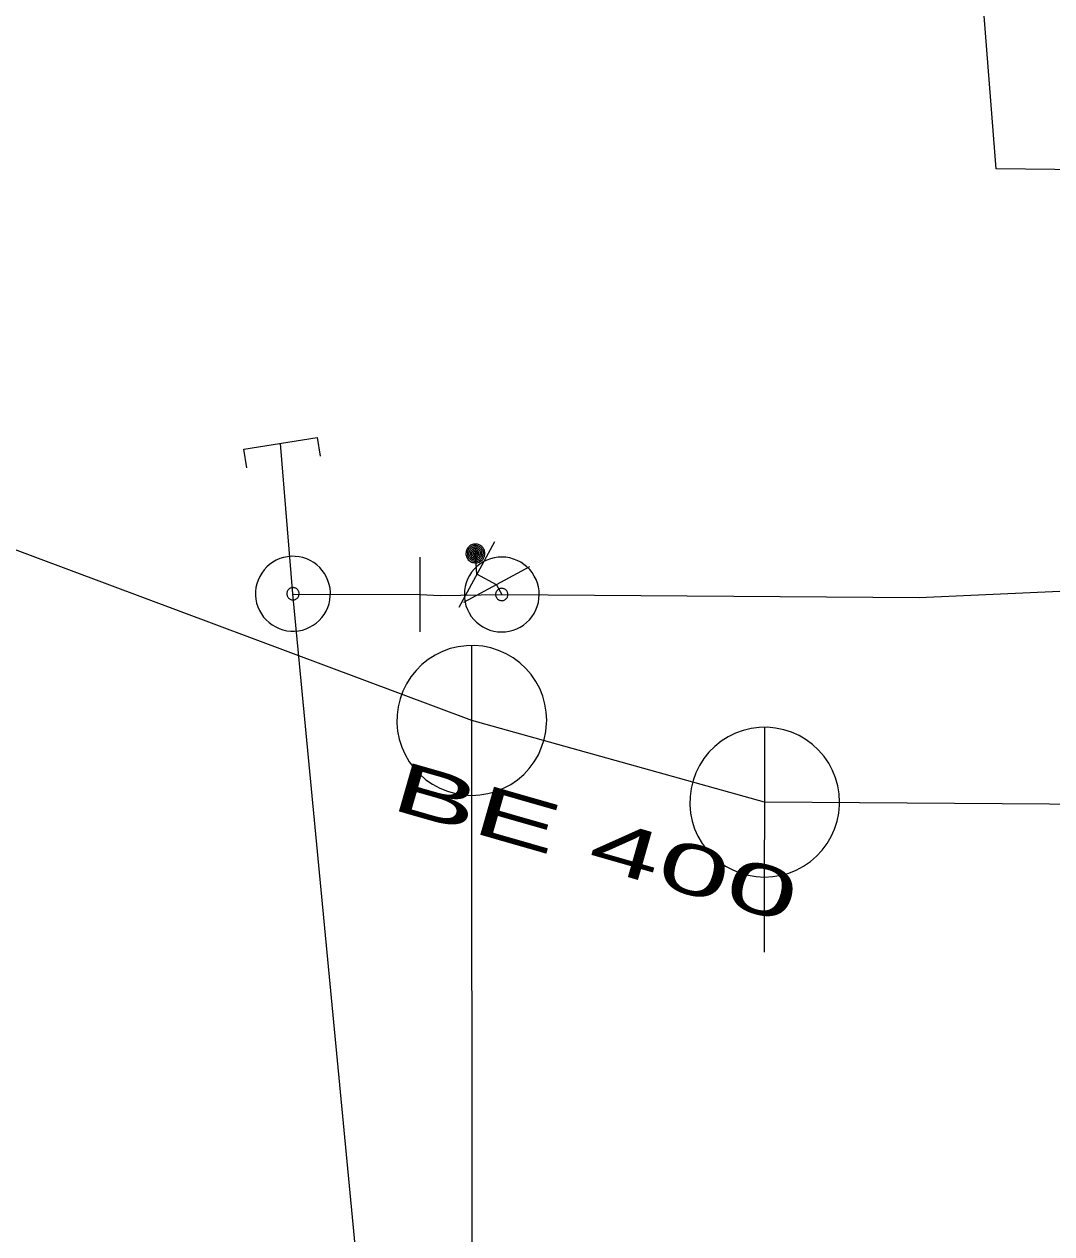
# Model space of a CAD drawing. Extents: x -688432 to -687974, y -973332 to -972704.
# Drawn here: x -688148.91 to -688135.2, y -972935.52 to -972919.38 of the extents above; entities that cross this region are included whole.
import ezdxf
from ezdxf.enums import TextEntityAlignment as Align

# ---------------------------------------------------------------- set-up
doc = ezdxf.new("R2010")
doc.units = 0
doc.header["$LTSCALE"] = 0.27
for name, color, linetype, lineweight in [('1', 7, 'Continuous', 25), ('14', 7, 'Continuous', 25), ('17', 7, 'Continuous', 25), ('22', 7, 'Continuous', 13), ('34', 7, 'Continuous', 13), ('47', 7, 'Continuous', 13), ('9', 7, 'Continuous', 13)]:
    doc.layers.add(name, color=color, linetype=linetype, lineweight=lineweight)

msp = doc.modelspace()

# ---------------------------------------------------------------- linework, layer by layer
at = {"layer": '1'}
msp.add_lwpolyline([(-688157.895, -972985.064), (-688131.748, -972983.489), (-688134.952, -972934.372), (-688122, -972934.52), (-688122.986, -972921.456), (-688135.938, -972921.308), (-688137.958, -972895.554), (-688157.714, -972894.909), (-688157.93, -972929.126), (-688173.215, -972938.189), (-688162.29, -972954.057)], close=True, dxfattribs=at)
at = {"layer": '14'}
for p, q in [((-688142.939, -972928.669), (-688206.6, -972904.874)), ((-688142.909, -972965.839), (-688142.939, -972928.669)), ((-688139.03, -972929.76), (-688142.939, -972928.669))]:
    msp.add_line(p, q, dxfattribs=at)
at = {"layer": '14', "lineweight": 13}
for p, q in [((-688142.609, -972926.859), (-688142.539, -972926.989)), ((-688143.629, -972926.989), (-688145.33, -972926.993))]:
    msp.add_line(p, q, dxfattribs=at)
msp.add_lwpolyline([(-688142.609, -972926.859), (-688142.87, -972926.719), (-688142.89, -972926.44)], dxfattribs=at)
at = {"layer": '14'}
msp.add_lwpolyline([(-688124.05, -972929.87), (-688127.949, -972929.829), (-688134.59, -972929.789), (-688139.03, -972929.76)], dxfattribs=at)
at = {"layer": '17'}
msp.add_line((-688145.326, -972926.979), (-688145.493, -972924.972), dxfattribs=at)
for points in [[(-688142.539, -972926.989), (-688136.969, -972927.03), (-688124.52, -972926.469), (-688116.5, -972926.3), (-688115.02, -972926.289), (-688112.359, -972926.21), (-688100.73, -972925.699), (-688087.609, -972926.17), (-688083.969, -972927.539), (-688080.94, -972929.1), (-688078.329, -972931.09), (-688076.37, -972933.14), (-688074.449, -972935.62), (-688070.85, -972940.129), (-688068.85, -972942.57), (-688067.02, -972944.8), (-688063.62, -972948.98), (-688063.329, -972949.34), (-688059.6, -972954.02), (-688058.039, -972955.829), (-688055.76, -972958.48), (-688051.969, -972962.76), (-688050.239, -972964.93)], [(-688050.85, -973016.992), (-688055.169, -973017.307), (-688064.057, -973021.728), (-688087.539, -973032.609), (-688093.627, -973034.653), (-688116.302, -973034.144), (-688128.092, -973024.28), (-688134.442, -973013.736), (-688141.05, -972971.647), (-688145.326, -972926.979)], [(-688143.629, -972926.989), (-688143.359, -972927), (-688142.539, -972926.989)]]:
    msp.add_lwpolyline(points, dxfattribs=at)
at = {"layer": '22'}
for p, q in [((-688142.939, -972930.669), (-688142.938, -972927.669)), ((-688139.03, -972931.76), (-688139.029, -972928.76))]:
    msp.add_line(p, q, dxfattribs=at)
for points in [[(-688141.939, -972928.669), (-688141.944, -972928.56), (-688141.962, -972928.452), (-688141.992, -972928.346), (-688142.032, -972928.245), (-688142.084, -972928.148), (-688142.146, -972928.058), (-688142.218, -972927.975), (-688142.298, -972927.901), (-688142.386, -972927.835), (-688142.48, -972927.78), (-688142.58, -972927.735), (-688142.685, -972927.702), (-688142.792, -972927.68), (-688142.901, -972927.67), (-688143.011, -972927.672), (-688143.119, -972927.686), (-688143.226, -972927.711), (-688143.329, -972927.748), (-688143.427, -972927.797), (-688143.519, -972927.855), (-688143.605, -972927.924), (-688143.682, -972928.001), (-688143.751, -972928.087), (-688143.81, -972928.179), (-688143.858, -972928.277), (-688143.895, -972928.38), (-688143.921, -972928.487), (-688143.935, -972928.595), (-688143.938, -972928.705), (-688143.928, -972928.814), (-688143.907, -972928.921), (-688143.873, -972929.025), (-688143.829, -972929.125), (-688143.774, -972929.22), (-688143.708, -972929.308), (-688143.634, -972929.388), (-688143.551, -972929.46), (-688143.461, -972929.522), (-688143.365, -972929.574), (-688143.263, -972929.615), (-688143.158, -972929.645), (-688143.05, -972929.663), (-688142.94, -972929.669), (-688142.831, -972929.663), (-688142.723, -972929.645), (-688142.618, -972929.616), (-688142.516, -972929.575), (-688142.419, -972929.523), (-688142.329, -972929.461), (-688142.246, -972929.39), (-688142.171, -972929.31), (-688142.106, -972929.222), (-688142.05, -972929.128), (-688142.006, -972929.028), (-688141.972, -972928.924), (-688141.95, -972928.816), (-688141.94, -972928.707)], [(-688138.03, -972929.76), (-688138.035, -972929.651), (-688138.053, -972929.543), (-688138.083, -972929.437), (-688138.123, -972929.336), (-688138.175, -972929.239), (-688138.237, -972929.149), (-688138.309, -972929.066), (-688138.389, -972928.992), (-688138.477, -972928.926), (-688138.571, -972928.871), (-688138.671, -972928.826), (-688138.776, -972928.793), (-688138.883, -972928.771), (-688138.992, -972928.761), (-688139.102, -972928.763), (-688139.21, -972928.777), (-688139.317, -972928.802), (-688139.42, -972928.839), (-688139.518, -972928.888), (-688139.61, -972928.946), (-688139.696, -972929.015), (-688139.773, -972929.092), (-688139.842, -972929.178), (-688139.901, -972929.27), (-688139.949, -972929.368), (-688139.986, -972929.471), (-688140.012, -972929.578), (-688140.026, -972929.686), (-688140.029, -972929.796), (-688140.019, -972929.905), (-688139.998, -972930.012), (-688139.964, -972930.116), (-688139.92, -972930.216), (-688139.865, -972930.311), (-688139.799, -972930.399), (-688139.725, -972930.479), (-688139.642, -972930.551), (-688139.552, -972930.613), (-688139.456, -972930.665), (-688139.354, -972930.706), (-688139.249, -972930.736), (-688139.141, -972930.754), (-688139.031, -972930.76), (-688138.922, -972930.754), (-688138.814, -972930.736), (-688138.709, -972930.707), (-688138.607, -972930.666), (-688138.51, -972930.614), (-688138.42, -972930.552), (-688138.337, -972930.481), (-688138.262, -972930.401), (-688138.197, -972930.313), (-688138.141, -972930.219), (-688138.097, -972930.119), (-688138.063, -972930.015), (-688138.041, -972929.907), (-688138.031, -972929.798)]]:
    msp.add_lwpolyline(points, close=True, dxfattribs=at)
at = {"layer": '34'}
for p, q in [((-688143.106, -972927.159), (-688142.632, -972926.279)), ((-688143.627, -972927.488), (-688143.629, -972926.489)), ((-688142.169, -972926.621), (-688143.049, -972927.095))]:
    msp.add_line(p, q, dxfattribs=at)
at = {"layer": '47'}
msp.add_lwpolyline([(-688145.942, -972925.299), (-688145.982, -972925.051), (-688145.003, -972924.892), (-688144.963, -972925.141)], dxfattribs=at)
for points in [[(-688145.304, -972927.478), (-688145.252, -972927.473), (-688145.2, -972927.463), (-688145.151, -972927.446), (-688145.103, -972927.426), (-688145.057, -972927.4), (-688145.014, -972927.369), (-688144.976, -972927.335), (-688144.94, -972927.296), (-688144.909, -972927.255), (-688144.882, -972927.209), (-688144.86, -972927.162), (-688144.844, -972927.112), (-688144.832, -972927.061), (-688144.827, -972927.009), (-688144.826, -972926.957), (-688144.831, -972926.905), (-688144.841, -972926.853), (-688144.858, -972926.803), (-688144.878, -972926.756), (-688144.904, -972926.71), (-688144.935, -972926.667), (-688144.969, -972926.628), (-688145.008, -972926.592), (-688145.049, -972926.561), (-688145.095, -972926.535), (-688145.142, -972926.513), (-688145.192, -972926.496), (-688145.243, -972926.485), (-688145.295, -972926.48), (-688145.347, -972926.479), (-688145.399, -972926.484), (-688145.451, -972926.494), (-688145.501, -972926.51), (-688145.548, -972926.531), (-688145.594, -972926.557), (-688145.637, -972926.587), (-688145.676, -972926.621), (-688145.712, -972926.66), (-688145.743, -972926.702), (-688145.769, -972926.748), (-688145.791, -972926.795), (-688145.808, -972926.844), (-688145.819, -972926.896), (-688145.824, -972926.948), (-688145.825, -972927), (-688145.82, -972927.052), (-688145.81, -972927.104), (-688145.794, -972927.153), (-688145.773, -972927.201), (-688145.747, -972927.247), (-688145.717, -972927.29), (-688145.683, -972927.328), (-688145.644, -972927.364), (-688145.602, -972927.395), (-688145.556, -972927.422), (-688145.509, -972927.444), (-688145.46, -972927.46), (-688145.408, -972927.472), (-688145.356, -972927.477)], [(-688142.039, -972926.992), (-688142.041, -972926.94), (-688142.049, -972926.888), (-688142.062, -972926.838), (-688142.08, -972926.789), (-688142.104, -972926.742), (-688142.132, -972926.697), (-688142.165, -972926.657), (-688142.202, -972926.62), (-688142.242, -972926.587), (-688142.285, -972926.557), (-688142.332, -972926.533), (-688142.381, -972926.515), (-688142.431, -972926.5), (-688142.483, -972926.492), (-688142.535, -972926.489), (-688142.587, -972926.491), (-688142.639, -972926.499), (-688142.69, -972926.512), (-688142.738, -972926.53), (-688142.785, -972926.554), (-688142.83, -972926.582), (-688142.871, -972926.615), (-688142.908, -972926.652), (-688142.941, -972926.692), (-688142.97, -972926.735), (-688142.994, -972926.782), (-688143.013, -972926.831), (-688143.027, -972926.881), (-688143.035, -972926.933), (-688143.038, -972926.985), (-688143.036, -972927.037), (-688143.028, -972927.089), (-688143.016, -972927.14), (-688142.997, -972927.188), (-688142.973, -972927.235), (-688142.946, -972927.28), (-688142.913, -972927.321), (-688142.876, -972927.358), (-688142.835, -972927.391), (-688142.792, -972927.42), (-688142.745, -972927.444), (-688142.697, -972927.463), (-688142.646, -972927.477), (-688142.594, -972927.485), (-688142.542, -972927.488), (-688142.49, -972927.486), (-688142.438, -972927.478), (-688142.388, -972927.466), (-688142.339, -972927.447), (-688142.292, -972927.423), (-688142.247, -972927.396), (-688142.207, -972927.363), (-688142.17, -972927.326), (-688142.137, -972927.285), (-688142.107, -972927.242), (-688142.083, -972927.195), (-688142.065, -972927.147), (-688142.05, -972927.096), (-688142.042, -972927.044)], [(-688145.322, -972927.06), (-688145.313, -972927.06), (-688145.305, -972927.058), (-688145.297, -972927.055), (-688145.289, -972927.052), (-688145.281, -972927.048), (-688145.275, -972927.042), (-688145.268, -972927.037), (-688145.262, -972927.031), (-688145.257, -972927.024), (-688145.253, -972927.016), (-688145.249, -972927.008), (-688145.246, -972927), (-688145.245, -972926.992), (-688145.243, -972926.984), (-688145.244, -972926.975), (-688145.244, -972926.966), (-688145.246, -972926.958), (-688145.249, -972926.95), (-688145.252, -972926.942), (-688145.256, -972926.934), (-688145.262, -972926.928), (-688145.267, -972926.921), (-688145.273, -972926.915), (-688145.28, -972926.909), (-688145.288, -972926.906), (-688145.296, -972926.902), (-688145.304, -972926.899), (-688145.312, -972926.898), (-688145.32, -972926.896), (-688145.329, -972926.897), (-688145.338, -972926.897), (-688145.346, -972926.899), (-688145.354, -972926.902), (-688145.362, -972926.905), (-688145.37, -972926.909), (-688145.376, -972926.914), (-688145.383, -972926.92), (-688145.389, -972926.926), (-688145.395, -972926.933), (-688145.398, -972926.941), (-688145.402, -972926.949), (-688145.405, -972926.957), (-688145.406, -972926.965), (-688145.408, -972926.973), (-688145.407, -972926.982), (-688145.407, -972926.991), (-688145.405, -972926.999), (-688145.402, -972927.007), (-688145.399, -972927.015), (-688145.395, -972927.023), (-688145.39, -972927.029), (-688145.384, -972927.036), (-688145.378, -972927.042), (-688145.371, -972927.047), (-688145.363, -972927.051), (-688145.355, -972927.055), (-688145.347, -972927.058), (-688145.339, -972927.059), (-688145.331, -972927.061)], [(-688142.457, -972926.989), (-688142.456, -972926.98), (-688142.458, -972926.972), (-688142.46, -972926.964), (-688142.463, -972926.956), (-688142.467, -972926.948), (-688142.472, -972926.941), (-688142.477, -972926.934), (-688142.483, -972926.928), (-688142.49, -972926.923), (-688142.497, -972926.918), (-688142.505, -972926.914), (-688142.513, -972926.911), (-688142.521, -972926.909), (-688142.529, -972926.907), (-688142.538, -972926.907), (-688142.547, -972926.906), (-688142.555, -972926.908), (-688142.563, -972926.91), (-688142.571, -972926.913), (-688142.579, -972926.917), (-688142.586, -972926.922), (-688142.593, -972926.927), (-688142.599, -972926.933), (-688142.605, -972926.94), (-688142.609, -972926.947), (-688142.613, -972926.955), (-688142.616, -972926.963), (-688142.618, -972926.971), (-688142.62, -972926.979), (-688142.62, -972926.988), (-688142.621, -972926.997), (-688142.619, -972927.005), (-688142.617, -972927.013), (-688142.614, -972927.021), (-688142.61, -972927.029), (-688142.606, -972927.036), (-688142.6, -972927.043), (-688142.594, -972927.049), (-688142.587, -972927.055), (-688142.58, -972927.059), (-688142.572, -972927.063), (-688142.564, -972927.066), (-688142.556, -972927.068), (-688142.548, -972927.07), (-688142.539, -972927.07), (-688142.53, -972927.071), (-688142.522, -972927.069), (-688142.514, -972927.067), (-688142.506, -972927.064), (-688142.498, -972927.06), (-688142.491, -972927.056), (-688142.484, -972927.05), (-688142.478, -972927.044), (-688142.473, -972927.037), (-688142.468, -972927.03), (-688142.464, -972927.022), (-688142.461, -972927.014), (-688142.459, -972927.006), (-688142.457, -972926.998)]]:
    msp.add_lwpolyline(points, close=True, dxfattribs=at)
at = {"layer": '9'}
for points in [[(-688143.016, -972926.44), (-688143.016, -972926.453), (-688143.014, -972926.466), (-688143.011, -972926.479), (-688143.006, -972926.491), (-688143, -972926.503), (-688142.993, -972926.514), (-688142.985, -972926.524), (-688142.975, -972926.534), (-688142.965, -972926.542), (-688142.954, -972926.549), (-688142.942, -972926.555), (-688142.93, -972926.56), (-688142.917, -972926.563), (-688142.904, -972926.565), (-688142.891, -972926.567), (-688142.878, -972926.566), (-688142.865, -972926.564), (-688142.852, -972926.561), (-688142.84, -972926.556), (-688142.828, -972926.55), (-688142.817, -972926.543), (-688142.807, -972926.535), (-688142.797, -972926.525), (-688142.789, -972926.515), (-688142.782, -972926.504), (-688142.776, -972926.492), (-688142.771, -972926.48), (-688142.768, -972926.467), (-688142.766, -972926.454), (-688142.764, -972926.441), (-688142.765, -972926.428), (-688142.767, -972926.415), (-688142.77, -972926.402), (-688142.775, -972926.39), (-688142.781, -972926.378), (-688142.788, -972926.367), (-688142.796, -972926.357), (-688142.806, -972926.347), (-688142.816, -972926.339), (-688142.827, -972926.332), (-688142.839, -972926.326), (-688142.851, -972926.321), (-688142.864, -972926.318), (-688142.877, -972926.316), (-688142.89, -972926.315), (-688142.903, -972926.315), (-688142.916, -972926.317), (-688142.929, -972926.32), (-688142.941, -972926.325), (-688142.953, -972926.331), (-688142.964, -972926.338), (-688142.974, -972926.346), (-688142.984, -972926.356), (-688142.992, -972926.366), (-688142.999, -972926.377), (-688143.005, -972926.389), (-688143.01, -972926.401), (-688143.013, -972926.414), (-688143.015, -972926.427)], [(-688142.996, -972926.44), (-688142.997, -972926.451), (-688142.995, -972926.462), (-688142.992, -972926.473), (-688142.988, -972926.483), (-688142.983, -972926.493), (-688142.977, -972926.502), (-688142.97, -972926.511), (-688142.962, -972926.519), (-688142.953, -972926.526), (-688142.944, -972926.532), (-688142.934, -972926.537), (-688142.924, -972926.541), (-688142.913, -972926.544), (-688142.902, -972926.547), (-688142.891, -972926.547), (-688142.88, -972926.547), (-688142.869, -972926.545), (-688142.858, -972926.542), (-688142.848, -972926.538), (-688142.838, -972926.533), (-688142.829, -972926.527), (-688142.82, -972926.52), (-688142.812, -972926.512), (-688142.805, -972926.503), (-688142.799, -972926.494), (-688142.794, -972926.484), (-688142.79, -972926.474), (-688142.787, -972926.463), (-688142.785, -972926.452), (-688142.784, -972926.441), (-688142.784, -972926.43), (-688142.786, -972926.419), (-688142.789, -972926.408), (-688142.793, -972926.398), (-688142.798, -972926.388), (-688142.804, -972926.379), (-688142.811, -972926.37), (-688142.819, -972926.362), (-688142.828, -972926.355), (-688142.837, -972926.349), (-688142.847, -972926.344), (-688142.857, -972926.34), (-688142.868, -972926.337), (-688142.879, -972926.335), (-688142.89, -972926.335), (-688142.901, -972926.334), (-688142.912, -972926.336), (-688142.923, -972926.339), (-688142.933, -972926.343), (-688142.943, -972926.348), (-688142.952, -972926.354), (-688142.961, -972926.361), (-688142.969, -972926.369), (-688142.976, -972926.378), (-688142.982, -972926.387), (-688142.987, -972926.397), (-688142.991, -972926.407), (-688142.994, -972926.418), (-688142.996, -972926.429)], [(-688142.977, -972926.44), (-688142.977, -972926.449), (-688142.976, -972926.458), (-688142.973, -972926.467), (-688142.97, -972926.475), (-688142.966, -972926.483), (-688142.961, -972926.491), (-688142.955, -972926.498), (-688142.949, -972926.504), (-688142.942, -972926.51), (-688142.934, -972926.515), (-688142.926, -972926.519), (-688142.918, -972926.522), (-688142.909, -972926.525), (-688142.9, -972926.526), (-688142.891, -972926.528), (-688142.882, -972926.527), (-688142.873, -972926.526), (-688142.864, -972926.523), (-688142.856, -972926.52), (-688142.848, -972926.516), (-688142.84, -972926.511), (-688142.833, -972926.505), (-688142.827, -972926.499), (-688142.821, -972926.492), (-688142.816, -972926.484), (-688142.812, -972926.476), (-688142.809, -972926.468), (-688142.806, -972926.459), (-688142.805, -972926.45), (-688142.803, -972926.441), (-688142.804, -972926.432), (-688142.805, -972926.423), (-688142.808, -972926.414), (-688142.811, -972926.406), (-688142.815, -972926.398), (-688142.82, -972926.39), (-688142.826, -972926.383), (-688142.832, -972926.377), (-688142.839, -972926.371), (-688142.847, -972926.366), (-688142.855, -972926.362), (-688142.863, -972926.359), (-688142.872, -972926.356), (-688142.881, -972926.355), (-688142.89, -972926.354), (-688142.899, -972926.354), (-688142.908, -972926.355), (-688142.917, -972926.358), (-688142.925, -972926.361), (-688142.933, -972926.365), (-688142.941, -972926.37), (-688142.948, -972926.376), (-688142.954, -972926.382), (-688142.96, -972926.389), (-688142.965, -972926.397), (-688142.969, -972926.405), (-688142.972, -972926.413), (-688142.975, -972926.422), (-688142.976, -972926.431)], [(-688142.957, -972926.44), (-688142.957, -972926.447), (-688142.956, -972926.454), (-688142.955, -972926.461), (-688142.952, -972926.467), (-688142.949, -972926.473), (-688142.945, -972926.479), (-688142.941, -972926.485), (-688142.936, -972926.49), (-688142.93, -972926.494), (-688142.924, -972926.498), (-688142.918, -972926.501), (-688142.912, -972926.504), (-688142.905, -972926.505), (-688142.898, -972926.508), (-688142.891, -972926.508), (-688142.884, -972926.508), (-688142.877, -972926.506), (-688142.87, -972926.505), (-688142.864, -972926.502), (-688142.857, -972926.499), (-688142.852, -972926.495), (-688142.846, -972926.491), (-688142.841, -972926.486), (-688142.837, -972926.48), (-688142.833, -972926.474), (-688142.83, -972926.468), (-688142.827, -972926.462), (-688142.825, -972926.455), (-688142.824, -972926.448), (-688142.823, -972926.441), (-688142.823, -972926.434), (-688142.824, -972926.427), (-688142.826, -972926.42), (-688142.829, -972926.414), (-688142.832, -972926.407), (-688142.836, -972926.402), (-688142.84, -972926.396), (-688142.845, -972926.391), (-688142.851, -972926.387), (-688142.856, -972926.383), (-688142.863, -972926.38), (-688142.869, -972926.377), (-688142.876, -972926.375), (-688142.883, -972926.374), (-688142.89, -972926.374), (-688142.897, -972926.374), (-688142.904, -972926.374), (-688142.911, -972926.376), (-688142.917, -972926.379), (-688142.923, -972926.382), (-688142.929, -972926.386), (-688142.935, -972926.39), (-688142.94, -972926.395), (-688142.944, -972926.401), (-688142.948, -972926.406), (-688142.951, -972926.413), (-688142.954, -972926.419), (-688142.955, -972926.426), (-688142.957, -972926.433)], [(-688142.937, -972926.44), (-688142.937, -972926.445), (-688142.937, -972926.45), (-688142.936, -972926.455), (-688142.934, -972926.459), (-688142.932, -972926.464), (-688142.929, -972926.468), (-688142.926, -972926.471), (-688142.922, -972926.475), (-688142.919, -972926.478), (-688142.915, -972926.481), (-688142.91, -972926.483), (-688142.906, -972926.485), (-688142.901, -972926.486), (-688142.896, -972926.488), (-688142.891, -972926.488), (-688142.886, -972926.488), (-688142.881, -972926.487), (-688142.876, -972926.486), (-688142.872, -972926.484), (-688142.867, -972926.482), (-688142.863, -972926.479), (-688142.859, -972926.476), (-688142.856, -972926.472), (-688142.853, -972926.469), (-688142.85, -972926.465), (-688142.848, -972926.46), (-688142.846, -972926.456), (-688142.845, -972926.451), (-688142.844, -972926.446), (-688142.843, -972926.441), (-688142.843, -972926.436), (-688142.844, -972926.431), (-688142.845, -972926.426), (-688142.847, -972926.422), (-688142.849, -972926.417), (-688142.852, -972926.413), (-688142.855, -972926.409), (-688142.858, -972926.406), (-688142.862, -972926.403), (-688142.866, -972926.4), (-688142.871, -972926.398), (-688142.875, -972926.396), (-688142.88, -972926.395), (-688142.885, -972926.394), (-688142.89, -972926.394), (-688142.895, -972926.394), (-688142.9, -972926.395), (-688142.905, -972926.395), (-688142.909, -972926.397), (-688142.914, -972926.399), (-688142.918, -972926.402), (-688142.921, -972926.405), (-688142.925, -972926.408), (-688142.928, -972926.412), (-688142.931, -972926.416), (-688142.933, -972926.421), (-688142.935, -972926.425), (-688142.936, -972926.43), (-688142.937, -972926.435)], [(-688142.917, -972926.44), (-688142.917, -972926.443), (-688142.918, -972926.446), (-688142.917, -972926.448), (-688142.916, -972926.451), (-688142.915, -972926.454), (-688142.913, -972926.456), (-688142.911, -972926.458), (-688142.909, -972926.46), (-688142.907, -972926.462), (-688142.905, -972926.464), (-688142.902, -972926.466), (-688142.899, -972926.467), (-688142.897, -972926.467), (-688142.894, -972926.468), (-688142.891, -972926.468), (-688142.888, -972926.468), (-688142.885, -972926.468), (-688142.882, -972926.467), (-688142.88, -972926.466), (-688142.877, -972926.465), (-688142.875, -972926.463), (-688142.872, -972926.461), (-688142.87, -972926.459), (-688142.869, -972926.457), (-688142.867, -972926.455), (-688142.866, -972926.452), (-688142.864, -972926.449), (-688142.864, -972926.447), (-688142.863, -972926.444), (-688142.862, -972926.441), (-688142.863, -972926.438), (-688142.863, -972926.435), (-688142.864, -972926.432), (-688142.865, -972926.43), (-688142.866, -972926.427), (-688142.868, -972926.425), (-688142.869, -972926.422), (-688142.871, -972926.42), (-688142.874, -972926.419), (-688142.876, -972926.417), (-688142.879, -972926.416), (-688142.881, -972926.415), (-688142.884, -972926.414), (-688142.887, -972926.414), (-688142.89, -972926.413), (-688142.893, -972926.414), (-688142.896, -972926.413), (-688142.898, -972926.415), (-688142.901, -972926.415), (-688142.904, -972926.416), (-688142.906, -972926.418), (-688142.908, -972926.419), (-688142.91, -972926.421), (-688142.912, -972926.424), (-688142.914, -972926.426), (-688142.915, -972926.429), (-688142.916, -972926.431), (-688142.917, -972926.434), (-688142.917, -972926.437)], [(-688142.898, -972926.44), (-688142.898, -972926.442), (-688142.898, -972926.442), (-688142.897, -972926.442), (-688142.897, -972926.444), (-688142.898, -972926.445), (-688142.896, -972926.445), (-688142.896, -972926.445), (-688142.896, -972926.447), (-688142.896, -972926.447), (-688142.895, -972926.448), (-688142.893, -972926.448), (-688142.893, -972926.448), (-688142.893, -972926.449), (-688142.891, -972926.449), (-688142.891, -972926.449), (-688142.89, -972926.449), (-688142.889, -972926.449), (-688142.889, -972926.448), (-688142.888, -972926.448), (-688142.886, -972926.448), (-688142.886, -972926.447), (-688142.886, -972926.447), (-688142.885, -972926.446), (-688142.885, -972926.446), (-688142.883, -972926.445), (-688142.883, -972926.444), (-688142.882, -972926.443), (-688142.882, -972926.443), (-688142.882, -972926.442), (-688142.882, -972926.441), (-688142.882, -972926.44), (-688142.882, -972926.439), (-688142.882, -972926.439), (-688142.883, -972926.438), (-688142.883, -972926.437), (-688142.884, -972926.436), (-688142.884, -972926.436), (-688142.885, -972926.435), (-688142.885, -972926.435), (-688142.886, -972926.434), (-688142.887, -972926.434), (-688142.888, -972926.433), (-688142.888, -972926.433), (-688142.889, -972926.433), (-688142.89, -972926.433), (-688142.891, -972926.433), (-688142.892, -972926.433), (-688142.892, -972926.433), (-688142.893, -972926.434), (-688142.894, -972926.433), (-688142.895, -972926.435), (-688142.895, -972926.435), (-688142.896, -972926.435), (-688142.896, -972926.435), (-688142.897, -972926.437), (-688142.897, -972926.438), (-688142.897, -972926.439), (-688142.898, -972926.439), (-688142.898, -972926.44)]]:
    msp.add_lwpolyline(points, close=True, dxfattribs=at)

# ---------------------------------------------------------------- texts
at = {"layer": '1', "width": 1.9}
msp.add_text('BE 400', height=0.6667, rotation=344, dxfattribs=at).set_placement((-688141.3749, -972930.6109), align=Align.CENTER)
msp.add_text('BE 400', height=0.6667, rotation=344, dxfattribs=at).set_placement((-688141.3749, -972930.6109), align=Align.CENTER)
msp.add_text('BE 400', height=0.6667, rotation=344, dxfattribs=at).set_placement((-688141.3749, -972930.6109), align=Align.CENTER)
msp.add_text('BE 400', height=0.6667, rotation=344, dxfattribs=at).set_placement((-688141.3749, -972930.6109), align=Align.CENTER)
msp.add_text('BE 400', height=0.6667, rotation=344, dxfattribs=at).set_placement((-688141.3749, -972930.6109), align=Align.CENTER)

doc.saveas('drawing.dxf')
